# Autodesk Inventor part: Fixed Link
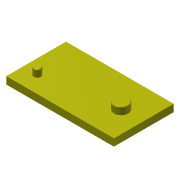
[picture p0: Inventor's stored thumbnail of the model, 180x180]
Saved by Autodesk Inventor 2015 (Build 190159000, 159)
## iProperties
Created: 2019-10
Part Number: Fixed Link
Material: 一般
Document SubType Name: Modeling
Designer: Kuan_Lun Hsu
Density: 1 g/cm^3
Appearance: 黃
Mass: 3480.48 g
Surface Area: 2751.41 cm^2
Volume: 3480.48 cm^3
Author: Kuan_Lun Hsu
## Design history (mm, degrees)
sketch "草圖1" dims "d4" = 60
  geometry: L1 (0, 220)-(200, 220); L2 (200, 220)-(200, 180); L3 (200, 180)-(0, 180); L4 (0, 180)-(0, 220); L5 (-21.213, 21.213)-(21.213, -21.213); L6 (21.213, -21.213)-(289.914, 247.487); L7 (289.914, 247.487)-(247.487, 289.914); L8 (247.487, 289.914)-(-21.213, 21.213); L9 (0, 0)-(200, 200); L10 (141.421, 141.421)-(247.487, 247.487); L11 (134.35, 148.492)-(240.416, 254.558); L12 (254.558, 240.416)-(148.492, 134.35); L13 (236.961, 152.108)-(300, 50); L14 (208.305, 143.231)-(242.687, 32.245); L15 (257.738, 173.749)-(341.553, 93.282); L16 (-60, 180)-(390, 180); L17 (390, 180)-(390, -70); L18 (390, -70)-(-60, -70); L19 (-60, -70)-(-60, 180); C1 r 10 at (200, 200); C2 r 15 at (0, 0); C3 r 30 at (300, 50); A1 r 10 centre (141.421, 141.421) between (134.35, 148.492) and (148.492, 134.35); A2 r 10 centre (247.487, 247.487) between (254.558, 240.416) and (240.416, 254.558); A3 r 60 centre (300, 50) between (242.687, 32.245) and (341.553, 93.282); A4 r 30 centre (236.961, 152.108) between (208.305, 143.231) and (257.738, 173.749); 4 further points
  constraints: 40 end point, 9 parallel, 9 tangent, 8 point on circle, 7 centre point, 4 coincident, 4 midpoint, 3 perpendicular, 2 horizontal, 2 vertical alignment, 1 collinear, 1 equal radius, 1 point on line, 5 other
  dimensions: "d0" = 40 distance between parallel lines of L3 L1; "d1" = 200 distance of L1.start L1.end; "d2" = 180 distance from line of point (0, 0) L3; "d3" = 20 diameter of C1; "d5" = 380 distance of L5.end L6.end; "d6" = 30 distance from line of L7 L10.end; "d7" = 150 distance of L11.start L11.end; "d8" = 60 diameter of A4; "d9" = 120 diameter of A3; "d10" = 120 distance of L13.start L13.end; "d11" = 300 horizontal distance of L13.end point (0, 0); "d12" = 50 vertical distance of point (0, 0) L13.end; "d13" = 60 distance between parallel lines of L19 L4; "d14" = 250 distance of L18.end L16.start; "d15" = 450 distance of L17.end L18.end; "d16" = 45 deg angle of L6 L18 (derived); "d17" = 30 diameter of C2; "d18" = 60 diameter of C3
extrude "擠出1" new body sketch "草圖1" distance "d19" = 30; taper "d20" = 0 deg
extrude "擠出2" join sketch "草圖1" distance "d21" = 30; taper "d22" = 0 deg
chamfer "倒角1" distance "d23" = 2; stored, may be unused: second distance "d24" = 2, angle "d25" = 45 deg
node "實體1"
